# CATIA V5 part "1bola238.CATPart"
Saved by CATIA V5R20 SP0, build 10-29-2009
Part number: 1bola238
Revision: ANY
Definition: UNKNOWN
Nomenclature: 1bola238
Source: Unknown
Bounding box of the stored display mesh (mm): x -1.19 to 1.19, y -1.19 to 1.19, z -1.19 to 1.19
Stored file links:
  C:\Users\Utente\Desktop\IO LAVORO\3D X SITO CF\CUMSA\3D files BE\BE 031115\1bola238.CATPart
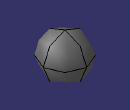
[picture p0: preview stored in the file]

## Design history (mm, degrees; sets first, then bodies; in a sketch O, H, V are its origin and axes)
Body1 "Revolución1" (main body)
  Solid1: solid without history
